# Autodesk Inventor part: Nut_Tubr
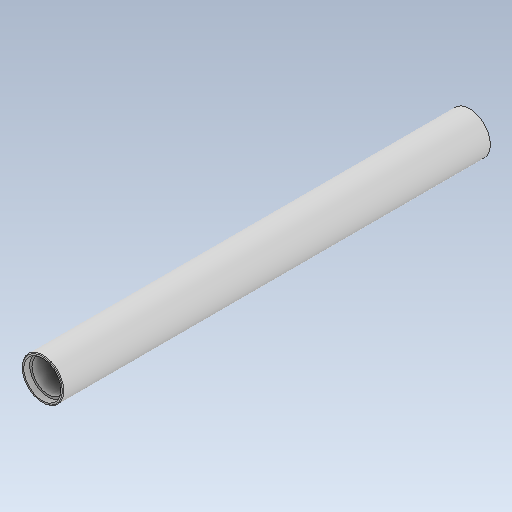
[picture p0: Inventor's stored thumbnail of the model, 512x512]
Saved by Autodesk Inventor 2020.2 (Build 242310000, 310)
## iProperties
Created: 2019-12
Part Number: Nut_Tubr
Material: Generic
Document SubType Name: Modeling
Designer: Patrick Everitt
Density: 1 g/cm^3
Appearance: Default
Description: 1.75OD 1.38ID TUBE 18 Lg
Author: Patrick Everitt
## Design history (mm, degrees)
sketch "Sketch1"
  geometry: C1 r 17.463 at (0, 0); C2 r 22.225 at (0, 0); 1 further point
  constraints: 2 centre point, 2 coincident
  dimensions: "d0" = 44.45 diameter of C2; "d1" = 34.925 diameter of C1
extrude "Extrusion1" new body sketch "Sketch1" distance "d2" = 457.2; taper "d3" = 0 deg
sketch "Sketch2"
  geometry: C1 r 19.844 at (0, 0); 1 further point
  constraints: 1 centre point, 1 coincident
  dimensions: "d4" = 39.6875 diameter of C1
extrude "Extrusion2" cut sketch "Sketch2" distance "d5" = 6.35; taper "d6" = 0 deg
chamfer "Chamfer1" distance "d7" = 0.762; stored, may be unused: second distance "d8" = 3.175, angle "d9" = 45 deg
body "Solid1"
